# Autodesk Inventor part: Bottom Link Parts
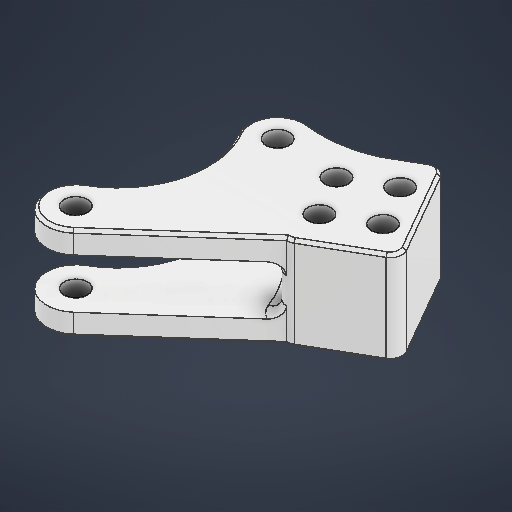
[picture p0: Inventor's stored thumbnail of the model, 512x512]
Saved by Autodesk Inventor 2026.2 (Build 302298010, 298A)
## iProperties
Created: 2026-05
Part Number: Bottom Link Parts
Material: ABS 플라스틱
Document SubType Name: Modeling
Designer: work
Density: 1.06 g/cm^3
Appearance: 매끄러움 - 흰색
Author: work
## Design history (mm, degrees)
sketch "스케치1"
  geometry: L1 (0, 0)-(-17.321, -10); L2 (-17.321, -10)-(-7.321, -27.321); L3 (-7.321, -27.321)-(56.423, -27.321); L4 (-35.507, -20.5)-(-25.507, -37.821); L5 (-25.507, -37.821)-(-11.651, -29.821); L6 (-11.651, -29.821)-(-21.651, -12.5); L7 (-21.651, -12.5)-(-35.507, -20.5); L8 (-35.507, -20.5)-(-11.651, -29.821); L9 (-25.507, -37.821)-(-21.651, -12.5); L10 (-12.321, -18.66)-(-23.579, -25.16); L11 (-29.043, -23.696)-(-25.043, -30.624); L12 (-25.043, -30.624)-(-18.115, -26.624); L13 (-18.115, -26.624)-(-22.115, -19.696); L14 (-22.115, -19.696)-(-29.043, -23.696); L15 (-29.043, -23.696)-(-18.115, -26.624); L16 (-25.043, -30.624)-(-22.115, -19.696); L17 (-3.316, 3.743)-(-21.651, -12.5); C1 r 2 at (0, 0); C2 r 2 at (-7.321, -27.321); C3 r 2 at (-22.115, -19.696); C4 r 2 at (-29.043, -23.696); C5 r 2 at (-18.115, -26.624); C6 r 2 at (-25.043, -30.624); A1 r 5 centre (0, 0) between (-3.316, 3.743) and (2.5, -4.33); A2 r 5 centre (-7.321, -27.321) between (-11.651, -29.821) and (-2.99, -24.821); A3 r 15 centre (10, -17.321) between (2.5, -4.33) and (-2.99, -24.821); A4 r 20 centre (-10.502, -52.117) between (-7.957, -32.28) and (-18.579, -33.821); 2 further points
  constraints: 34 end point, 10 centre point, 9 point on circle, 8 coincident, 8 midpoint, 5 parallel, 4 perpendicular, 4 tangent, 1 horizontal
  dimensions: "d0" = 4 diameter of C1; "d1" = 20 distance of L1.start L1.end; "d2" = 4 diameter of C2; "d3" = 20 distance of L1.end L2.end; "d4" = 30 deg angle of L3 L1; "d5" = 10 diameter of A1; "d6" = 10 diameter of A2; "d7" = 20 distance of L5.end L6.end; "d8" = 6 distance between parallel lines of L5 L12; "d9" = 4 distance between parallel lines of L4 L11; "d10" = 16 distance of L6.end L4.start; "d11" = 4 diameter of C3; "d12" = 4 diameter of C4; "d13" = 4 diameter of C5; "d14" = 4 diameter of C6; "d15" = 15 radius of A3; "d16" = 20 radius of A4
extrude "돌출1" new body sketch "스케치1" distance "d17" = 16; taper "d18" = 0 deg
node "작업 평면1"
sketch "스케치2"
  geometry: L1 (25.507, -37.821)-(18.579, -33.821) reference; L2 (3.316, 3.743)-(21.651, -12.5) reference; L3 (3.316, 3.743)-(21.651, -12.5) reference; L4 (25.507, -37.821)-(18.579, -33.821) reference; L5 (35.507, -20.5)-(25.507, -37.821) reference; L6 (21.651, -12.5)-(35.507, -20.5) reference; C1 r 2 at (7.321, -27.321) reference; C2 r 2 at (25.043, -30.624) reference; C3 r 2 at (18.115, -26.624) reference; C4 r 2 at (29.043, -23.696) reference; C5 r 2 at (22.115, -19.696) reference; C6 r 2 at (0, 0) reference; C7 r 6.5 at (7.321, -27.321); A1 r 5 centre (0, 0) between (3.316, 3.743) and (-2.5, -4.33) reference; A2 r 15 centre (-10, -17.321) between (2.99, -24.821) and (-2.5, -4.33) reference; A3 r 5 centre (7.321, -27.321) between (2.99, -24.821) and (7.957, -32.28) reference; A4 r 20 centre (10.502, -52.117) between (18.579, -33.821) and (7.957, -32.28) reference; A5 r 25 centre (-2.402, -5.683) between (15.094, -23.541) and (21.651, -12.5); 7 further points
  constraints: 2 centre point, 2 point on circle, 1 coincident, 1 concentric, 5 other
  dimensions: "d19" = 13 diameter of C7; "d20" = 25 radius of A5
extrude "돌출2" cut sketch "스케치2" stored distance "d21" = 8.5; taper "d22" = 0 deg
fillet "모깎기1" dims "d23" = 2
chamfer "모따기1" distance "d24" = 0.5; stored, may be unused: second distance "d25" = 2, angle "d26" = 45 deg
node "솔리드1"
node "투영된 루프1"
other parameters: "sa_0" = 4
